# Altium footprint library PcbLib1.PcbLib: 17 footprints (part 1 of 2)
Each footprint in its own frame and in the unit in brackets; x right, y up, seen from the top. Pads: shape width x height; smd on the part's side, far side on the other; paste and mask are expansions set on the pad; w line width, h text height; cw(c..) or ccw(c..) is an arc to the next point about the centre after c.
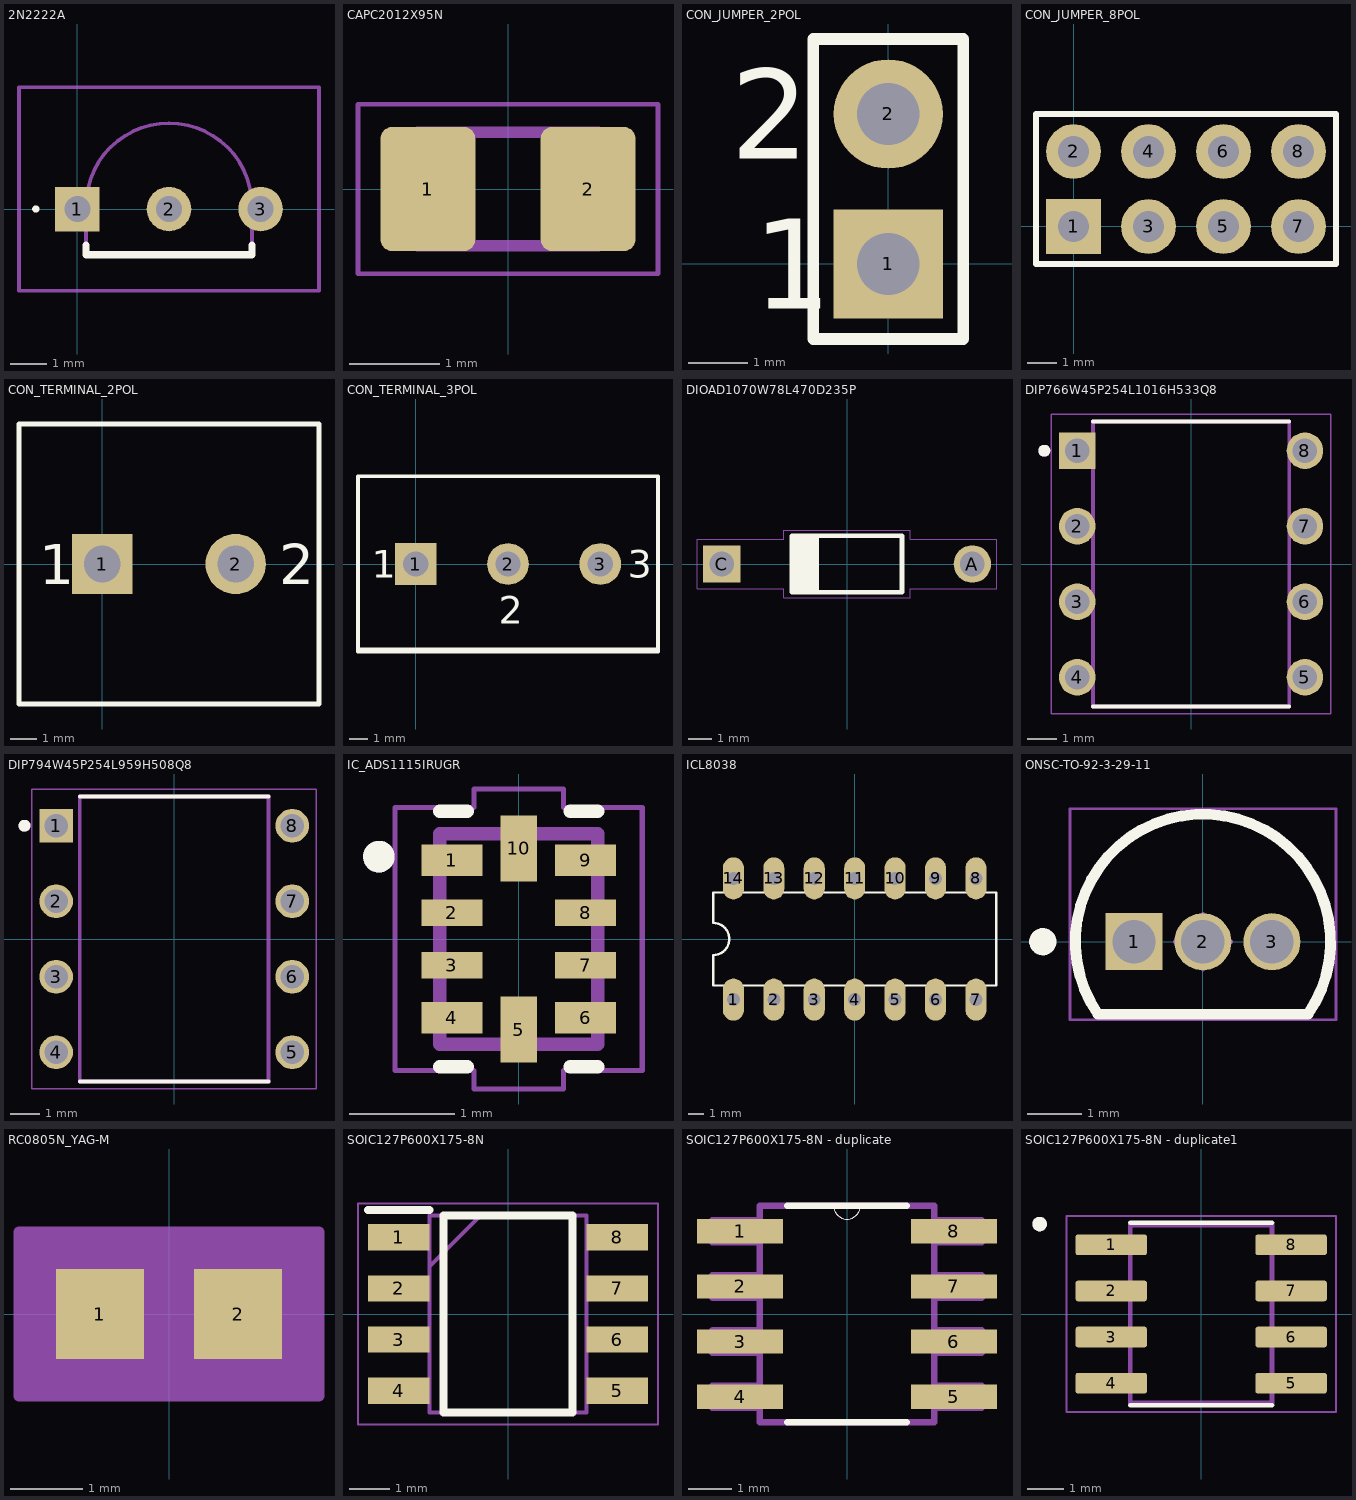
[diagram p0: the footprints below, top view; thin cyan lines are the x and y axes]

## 2N2222A [mm]
pads (3):
  rect 1.234x1.234 hole 0.72: 1(0,0)
  round 1.234 hole 0.72: 2(2.54,0) 3(5.08,0)
Top Overlay:
  lines w0.1: -1.2,0 cw(c-1.15,0) -1.1,0 cw(c-1.15,0) -1.2,0
  lines w0.2: 0.24,-1 0.24,-1.27 4.84,-1.27 4.84,-1
Mechanical 13:
  lines w0.1: 0.24,-1.27 0.24,0.08 cw(c2.54,0.08) 4.84,0.08 4.84,-1.27 0.24,-1.27
Mechanical 15:
  lines w0.1: -1.617,-2.27 -1.617,3.38 6.697,3.38 6.697,-2.27 -1.617,-2.27
3D body "2N2222A.stp": height 7.46, standoff -9.64, extent -0.2,-1.25 5.28,2.35

## CAPC2012X95N [mm]
pads (2):
  rrect25% 1.05x1.38 smd: 1(-0.888,0) 2(0.888,0)
Mechanical 13:
  lines w0.127: -1,-0.63 1,-0.63 1,0.63 -1,0.63 -1,-0.63
Mechanical 15:
  lines w0.05: -1.663,-0.94 1.663,-0.94 1.663,0.94 -1.663,0.94 -1.663,-0.94
3D body "step_temp.STEP": height 0.95, standoff 0, extent -1,-0.625 1,0.625

## CON_JUMPER_2POL [mm] "Jumper"
pads (2):
  rect 1.85x1.85 hole 1.05: 1(0,0)
  round 1.85 hole 1.05: 2(0,2.54)
Top Overlay:
  lines w0.2: -1.27,-1.27 1.27,-1.27 1.27,3.81 -1.27,3.81 -1.27,2.54 -1.27,-1.27
  text "1" at -2.286,-0.762 h1.52
  text "2" at -2.667,1.778 h1.52

## CON_JUMPER_8POL [mm] "Jumper"
pads (8):
  rect 1.85x1.85 hole 1.05: 1(0,0)
  round 1.85 hole 1.05: 2(0,2.54) 3(2.54,0) 4(2.54,2.54) 5(5.08,0) 6(5.08,2.54) 7(7.62,0) 8(7.62,2.54)
Top Overlay:
  lines w0.2: -1.27,-1.27 8.89,-1.27 8.89,3.81 -1.27,3.81 -1.27,-1.27

## CON_TERMINAL_2POL [mm] "Terminal Screw"
pads (2):
  rect 2.3x2.3 hole 1.4: 1(0,0)
  round 2.3 hole 1.4: 2(5.08,0)
Top Overlay:
  lines w0.2: -3.175,-5.334 8.255,-5.334 8.255,5.334 -3.175,5.334 -3.175,0 -3.175,-5.334
  text "1" at -2.413,-0.762 h1.52
  text "2" at 6.731,-0.762 h1.52

## CON_TERMINAL_3POL [mm] "Terminal Screw"
pads (3):
  rect 2.3x2.3 hole 1.4: 1(0,0)
  round 2.3 hole 1.4: 2(5.08,0) 3(10.16,0)
Top Overlay:
  lines w0.2: -3.048,-4.699 13.208,-4.699 ; -3.175,-4.826 13.335,-4.826 13.335,4.826 -3.175,4.826 -3.175,0 -3.175,-4.826
  text "1" at -2.413,-0.762 h1.52
  text "2" at 4.572,-3.302 h1.52
  text "3" at 11.684,-0.762 h1.52

## DIOAD1070W78L470D235P [mm]
pads (2):
  round 1.6 hole 1.05: A(5.35,0)
  rect 1.6x1.6 / inner round 1.6 / far side rect 1.6x1.6 hole 1.05: C(-5.35,0)
Top Overlay:
  region: -1.2,-1.202 -2.403,-1.202 -2.403,1.2 -1.2,1.2
  lines w0.2: -2.35,-1.2 -2.35,1.2 2.35,1.2 2.35,-1.2 -2.35,-1.2
Mechanical 15:
  lines w0.05: -6.4,-1.05 -6.4,1.05 -2.7,1.05 -2.7,1.45 2.7,1.45 2.7,1.05 6.4,1.05 6.4,-1.05 2.7,-1.05 2.7,-1.45 -2.7,-1.45 -2.7,-1.05 -6.4,-1.05
3D body "step_temp.STEP": height 2.7, standoff -21.05, extent -5.743,-1.35 5.743,1.35

## DIP766W45P254L1016H533Q8 [mm]
pads (8):
  rect 1.23x1.23 / inner round 1.23 / far side rect 1.23x1.23 hole 0.82: 1(-3.83,3.81)
  round 1.23 hole 0.82: 2(-3.83,1.27) 3(-3.83,-1.27) 4(-3.83,-3.81) 5(3.83,-3.81) 6(3.83,-1.27) 7(3.83,1.27) 8(3.83,3.81)
Top Overlay:
  circle w0.2: c-4.935,3.81 r0.1
  lines w0.127: -3.303,-4.795 3.303,-4.795 ; -3.303,4.795 3.303,4.795
Mechanical 13:
  circle w0.2: c-4.935,3.81 r0.1
  lines w0.127: -3.303,-4.795 3.303,-4.795 3.303,4.795 -3.303,4.795 -3.303,-4.795
Mechanical 15:
  lines w0.05: -4.695,-5.045 4.695,-5.045 4.695,5.045 -4.695,5.045 -4.695,-5.045
3D body "step_temp.STEP": height 5.33, standoff -3, extent -4.003,-4.94 4.003,4.94

## DIP794W45P254L959H508Q8 [mm]
pads (8):
  rect 1.13x1.13 / inner round 1.13 / far side rect 1.13x1.13 hole 0.78 mask+0.102: 1(-3.97,3.81)
  round 1.13 hole 0.78 mask+0.102: 2(-3.97,1.27) 3(-3.97,-1.27) 4(-3.97,-3.81) 5(3.97,-3.81) 6(3.97,-1.27) 7(3.97,1.27) 8(3.97,3.81)
Top Overlay:
  circle w0.2: c-5.035,3.81 r0.1
  lines w0.127: -3.175,-4.795 3.175,-4.795 ; -3.175,4.795 3.175,4.795
Mechanical 13:
  circle w0.2: c-5.035,3.81 r0.1
  lines w0.127: -3.175,-4.795 -3.175,4.795 3.175,4.795 3.175,-4.795 -3.175,-4.795
Mechanical 15:
  lines w0.05: -4.785,-5.045 -4.785,5.045 4.785,5.045 4.785,-5.045 -4.785,-5.045
3D body "step_temp.STEP": height 5.08, standoff -3.18, extent -4.095,-4.795 4.095,4.795

## IC_ADS1115IRUGR [mm]
pads (10):
  rect 0.58x0.3 smd paste-0.025: 1(-0.635,0.75) 4(-0.635,-0.75) 6(0.635,-0.75) 9(0.635,0.75)
  rect 0.58x0.25 smd paste-1: 2(-0.635,0.25) 3(-0.635,-0.25) 7(0.635,-0.25) 8(0.635,0.25)
  rect 0.35x0.63 smd paste-0.025: 5(0,-0.86) 10(0,0.86)
Top Overlay:
  circle w0.2: c-1.328,0.783 r0.05
  lines w0.127: -0.75,-1.213 -0.488,-1.213 ; -0.75,1.213 -0.488,1.213 ; 0.488,-1.213 0.75,-1.213 ; 0.488,1.213 0.75,1.213
Top Paste:
  region: -0.37,-0.375 -0.9,-0.375 -0.9,-0.125 -0.37,-0.125
  region: -0.37,0.125 -0.9,0.125 -0.9,0.375 -0.37,0.375
  region: 0.9,-0.375 0.37,-0.375 0.37,-0.125 0.9,-0.125
  region: 0.9,0.125 0.37,0.125 0.37,0.375 0.9,0.375
Mechanical 13:
  circle w0.2: c-1.328,0.783 r0.05
  lines w0.127: -0.75,-1 0.75,-1 0.75,1 -0.75,1 -0.75,-1
Mechanical 15:
  lines w0.05: -1.175,-1.25 -1.175,1.25 -0.425,1.25 -0.425,1.425 0.425,1.425 0.425,1.25 1.175,1.25 1.175,-1.25 0.425,-1.25 0.425,-1.425 -0.425,-1.425 -0.425,-1.25 -1.175,-1.25
3D body "step_temp.STEP": height 0.4, standoff 0, extent -0.75,-1 0.75,1

## ICL8038 [mil]
pads (14):
  oval 52x104 hole 32: 1(-300,-150) 2(-200,-150) 3(-100,-150) 4(0,-150) 5(100,-150) 6(200,-150) 7(300,-150) 8(300,150) 9(200,150) 10(100,150) 11(0,150) 12(-100,150) 13(-200,150) 14(-300,150)
Top Overlay:
  lines w6: -350,-115 -350,-40 ccw(c-350,0) -350,40 -350,115 350,115 350,-115 -350,-115

## ONSC-TO-92-3-29-11 [mm] "TO, 3-Leads, Body Dia 4.7mm, Pitch 1.27mm"
height 7.87
pads (3):
  rect 1.05x1.05 hole 0.8: 1(-1.27,0)
  round 1.05 hole 0.8: 2(0,0) 3(1.27,0)
Top Overlay:
  circle w0.25: c-2.95,0 r0.125
  lines w0.2: -1.934,-1.335 cw(c0,0) 1.934,-1.335 -1.934,-1.335
Mechanical 13:
  lines w0.1: -1.934,-1.335 cw(c0,0) 1.934,-1.335 -1.934,-1.335
Mechanical 15:
  lines w0.05: -2.45,-1.435 2.45,-1.435 2.45,2.45 -2.45,2.45 -2.45,-1.435
  lines w0.1: -0.5,0 0.5,0 ; 0,-0.5 0,0.5
3D body: height 7.87, standoff 2.54, extent -2.349,-1.334 2.357,2.359

## RC0805N_YAG-M [mil]
pads (2):
  rect 48x49 smd paste+0 mask+0: 1(-37.5,0) 2(37.5,0)
Mechanical 13:
  lines w1: -39.5,-23.5 -39.5,23.5 ; -39.5,-23.5 -13.5,-23.5 -13.5,23.5 -39.5,23.5 ; -39.5,-23.5 39.5,-23.5 ; -39.5,-23.5 -39.5,23.5 ; -39.5,23.5 39.5,23.5 ; 39.5,-23.5 13.5,-23.5 13.5,23.5 39.5,23.5 ; 39.5,-23.5 39.5,23.5 ; 39.5,-23.5 39.5,23.5
Mechanical 15:
  region: 81.5,-44.5 -81.5,-44.5 -81.5,44.5 81.5,44.5
  lines w6: -81.5,-44.5 -81.5,44.5 81.5,44.5 81.5,-44.5 -81.5,-44.5
3D body "RC0805N_YAG.step": height 27.99, standoff 0, extent -39.49,-23.5 39.49,23.5

## SOIC127P600X175-8N [mm]
pads (8):
  rect 1.525x0.65 smd: 1(-2.712,1.905) 2(-2.712,0.635) 3(-2.712,-0.635) 4(-2.712,-1.905) 5(2.712,-1.905) 6(2.712,-0.635) 7(2.712,0.635) 8(2.712,1.905)
Top Overlay:
  lines w0.2: -3.475,2.58 -1.95,2.58 ; -1.6,-2.45 1.6,-2.45 1.6,2.45 -1.6,2.45 -1.6,-2.45
Mechanical 13:
  lines w0.1: -1.95,1.18 -0.68,2.45 ; -1.95,-2.45 1.95,-2.45 1.95,2.45 -1.95,2.45 -1.95,-2.45
Mechanical 15:
  lines w0.05: -3.725,-2.75 3.725,-2.75 3.725,2.75 -3.725,2.75 -3.725,-2.75
3D body "NE555DR.stp": height 1.75, standoff 0, extent -3,-2.45 3,2.45

## SOIC127P600X175-8N - duplicate [mil]
pads (8):
  rect 78x22 smd: 1(-97,75) 2(-97,25) 3(-97,-25) 4(-97,-75) 5(97,-75) 6(97,-25) 7(97,25) 8(97,75)
Top Overlay:
  lines w0: -12,98 ccw(c0,98) 12,98
  lines w6: -54,-98 54,-98 ; -54,98 -12,98 12,98 54,98
Mechanical 13:
  lines w0: -12,98 ccw(c0,98) 12,98
  lines w6: -122,-85 -122,-65 -79,-65 -79,-85 -122,-85 ; -122,-35 -122,-15 -79,-15 -79,-35 -122,-35 ; -122,15 -122,35 -79,35 -79,15 -122,15 ; -122,65 -122,85 -79,85 -79,65 -122,65 ; -79,-98 79,-98 79,98 12,98 -12,98 -79,98 -79,-98 ; 79,-85 79,-65 122,-65 122,-85 79,-85 ; 79,-35 79,-15 122,-15 122,-35 79,-35 ; 79,15 79,35 122,35 122,15 79,15 ; 79,65 79,85 122,85 122,65 79,65
3D body "step_temp.STEP": height 68.9, standoff 0, extent -118.11,-96.46 118.11,96.46

## SOIC127P600X175-8N - duplicate1 [mm]
pads (8):
  rrect25% 1.97x0.57 smd paste+0 mask+0.102: 1(-2.475,1.905) 2(-2.475,0.635) 3(-2.475,-0.635) 4(-2.475,-1.905) 5(2.475,-1.905) 6(2.475,-0.635) 7(2.475,0.635) 8(2.475,1.905)
Top Overlay:
  circle w0.2: c-4.445,2.475 r0.1
  lines w0.127: -1.95,-2.51 1.95,-2.51 ; -1.95,2.51 1.95,2.51
Mechanical 13:
  circle w0.2: c-4.445,2.475 r0.1
  lines w0.127: -1.95,-2.45 -1.95,2.45 1.95,2.45 1.95,-2.45 -1.95,-2.45
Mechanical 15:
  lines w0.05: -3.71,-2.7 -3.71,2.7 3.71,2.7 3.71,-2.7 -3.71,-2.7
3D body "step_temp.STEP": height 1.75, standoff 0, extent -2.995,-2.452 2.995,2.452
